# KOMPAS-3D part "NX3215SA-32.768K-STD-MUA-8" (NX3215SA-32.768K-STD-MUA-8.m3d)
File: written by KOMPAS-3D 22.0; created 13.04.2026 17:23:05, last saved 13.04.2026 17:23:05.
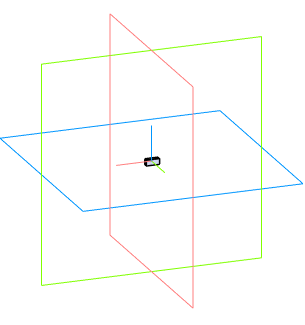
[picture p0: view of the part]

Document properties: Автор: Andrey; Полное имя файла: C:\Users\User1\Documents\NX3215SA-32.768K-STD-MUA-8.m3d

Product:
- Part/product: NX3215SA-32.768K-STD-MUA-8

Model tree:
1. Операция без истории:1
2. Операция без истории:2
3. Операция без истории:3
4. Операция без истории:4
